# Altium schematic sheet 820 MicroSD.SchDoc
size Letter; Organization: Toradex Solutions Inc.; Address1: 6415 Northwest Drive; Address2: Mississauga, ON, L4V 1X1; Address3: Canada
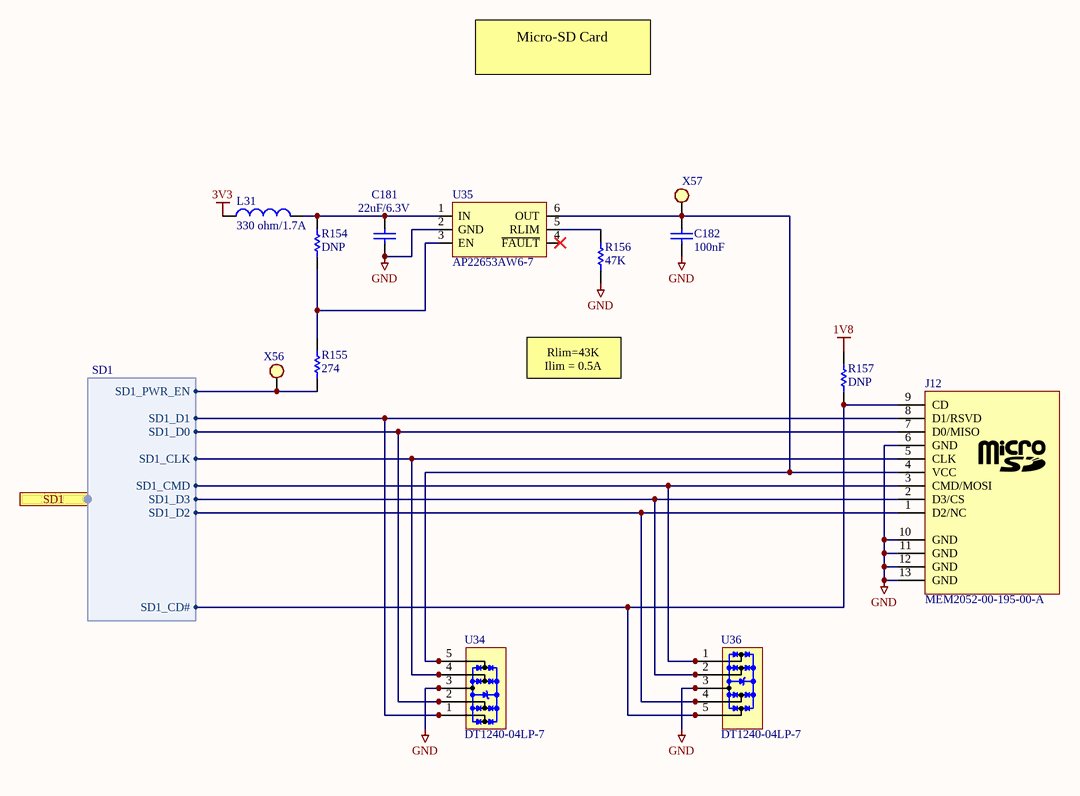
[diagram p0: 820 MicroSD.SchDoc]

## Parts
C181  22uF/6.3V  [C0402_CAPC1005L]
C182  100nF  [C0402_CAPC1005L]
J12  MEM2052-00-195-00-A  [MEM2051-00-195-00-A_revC]
L31  value 330 ohm/1.7A  [INDC1608x095]  (hidden comment: 0405-Fer-0603-330ohm/1.7A)
R154  value DNP  [R/0603]  (hidden comment: 0000-Res-0603-DNP)
R155  value 274  [R/0603]  (hidden comment: 0728-Res-0603-274ohm)
R156  value 47K  [R/0603]  (hidden comment: 0042-Res-0603-47K)
R157  value DNP  [R/0603]  (hidden comment: 0000-Res-0603-DNP)
U34  DT1240-04LP-7  [10-UFDFN]
U35  AP22653AW6-7  [sot23-6]
U36  DT1240-04LP-7  [10-UFDFN]
X56  000-TestPoint2  [TestPoint_3]  (value not drawn)
X57  000-TestPoint2  [TestPoint_3]  (value not drawn)

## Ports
SD1 (harness SD1)

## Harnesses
SD1: SD1_D2, SD1_D3, SD1_CMD, SD1_PWR_EN, SD1_CLK, SD1_D0, SD1_D1, SD1_CD#

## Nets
1V8: R157.2
3V3: L31.1
GND: C181.1 C182.1 J12.6(GND) J12.10(GND) J12.11(GND) J12.12(GND) J12.13(GND) R156.2 U34.3(GND) U34.8(GND) U35.2(GND) U36.3(GND) U36.8(GND)
NetC181_2: C181.2 L31.2 R154.2 U35.1(IN)
NetC182_2: C182.2 J12.4(VCC) U34.5(IO4) U34.6(NC) U35.6(OUT) X57.1
NetJ12_1: J12.1(D2/NC) U36.4(IO3) U36.7(NC) ; port SD1.SD1_D2
NetJ12_2: J12.2(D3/CS) U36.2(IO2) U36.9(NC) ; port SD1.SD1_D3
NetJ12_3: J12.3(CMD/MOSI) U36.1(IO1) U36.10(NC) ; port SD1.SD1_CMD
NetJ12_5: J12.5(CLK) U34.4(IO3) U34.7(NC) ; port SD1.SD1_CLK
NetJ12_7: J12.7(D0/MISO) U34.2(IO2) U34.9(NC) ; port SD1.SD1_D0
NetJ12_8: J12.8(D1/RSVD) U34.1(IO1) U34.10(NC) ; port SD1.SD1_D1
NetJ12_9: J12.9(CD) R157.1 U36.5(IO4) U36.6(NC) ; port SD1.SD1_CD#
NetR154_1: R154.1 R155.1 U35.3(EN)
NetR155_2: R155.2 X56.1 ; port SD1.SD1_PWR_EN
NetR156_1: R156.1 U35.5(RLIM)

Not connected (* = marked no-connect by the designer): U35 4(~{FAULT})*

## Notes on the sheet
- Micro-SD Card
- Rlim=43K
  Ilim = 0.5A

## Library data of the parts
C181 = 2404-Cap-0402-22uF/6.3V: (-55 to 85 DegC) CAP CER 22UF 6.3V 20% X5R 0402; MfrNo: GRM155R60J226ME11D; Mfr: Murata; PN: 2404
C182 = 1566-Cap-0402-100nF/50V: (-55 to 125 DegC AEC) Cap Ceramic 0.1uF 50V X7R 10% 0402; MfrNo: GRT155R71H104KE01D; Mfr: Murata; Alt: CL05B104KB54PNC,GCM155R71H104ME02D,GCM155R71H104KE02D,GCM155R71H104KE02J; PN: 1566
J12 = 1776-Conn-MicroSD: (-40 to 85 DegC) CONN MICRO SD CARD PUSH-PUSH R/A, OPEN; Mfr: Global Connector Technology; PN: 1776; Alt: PN 1404
L31 = 0405-Fer-0603-330ohm/1.7A: (-55 to 125 DegC) FERRITE BEAD 330 OHM 0603 1.7A 80mohm, typ 48mohm; Mfr: TDK Corporation; MfrNo: MPZ1608S331ATA00; PN: 405; TR: 445-5221-2-ND; DR: 445-5221-6-ND; DR2: 810-MPZ1608S331ATA00
R154 R157 = 0000-Res-0603-DNP: RES 0603
R155 = 0728-Res-0603-274ohm: RES SMD 274 OHM 1% 1/10W 0603; MfrNo: RC0603FR-07274RL; Mfr: Yageo; PN: 728; TR: 311-274HRTR-ND
R156 = 0042-Res-0603-47K: RES 47.0K OHM 1/10W 1% 0603 SMD; Mfr: Yageo; MfrNo: RC0603FR-0747KL; Alt: RHM47.0KCFCT-ND; Alt2: RHM47.0KHCT-ND; PN: 42; TR: 311-47.0KHRTR-ND
U34 U36 = 1657-DT1240-04LP-7: (-55 to 85 DegC) IC TVS DIODE 4ch Vrm:5.5V Vcl:11V@5.5A 10-UFDFN 0.5mm; Mfr: Diodes; PN: 1657
U35 = 1475-AP22653: (-40 to 85 DegC) IC PWR SWITCH 3-5.5V EN-Active-High ENth:1.5V With-Discharge 65mohm typ ADJ 0.1-2.1A 6SSOP; Mfr: Diodes; PN: 1475; Note: Similar: BD2222G, BD2242G, TPS25221, TPS2553, RT9728A, RT9728B, RT9728C, AP2553, MIC2009YM6, MIC2019YM6, MIC2009A-1YM6,MIC2019A-1YM6
X56 X57 = 000-TestPoint2: TestPoint SMD; Note: PCB footprint only, no parts to buy or assemble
